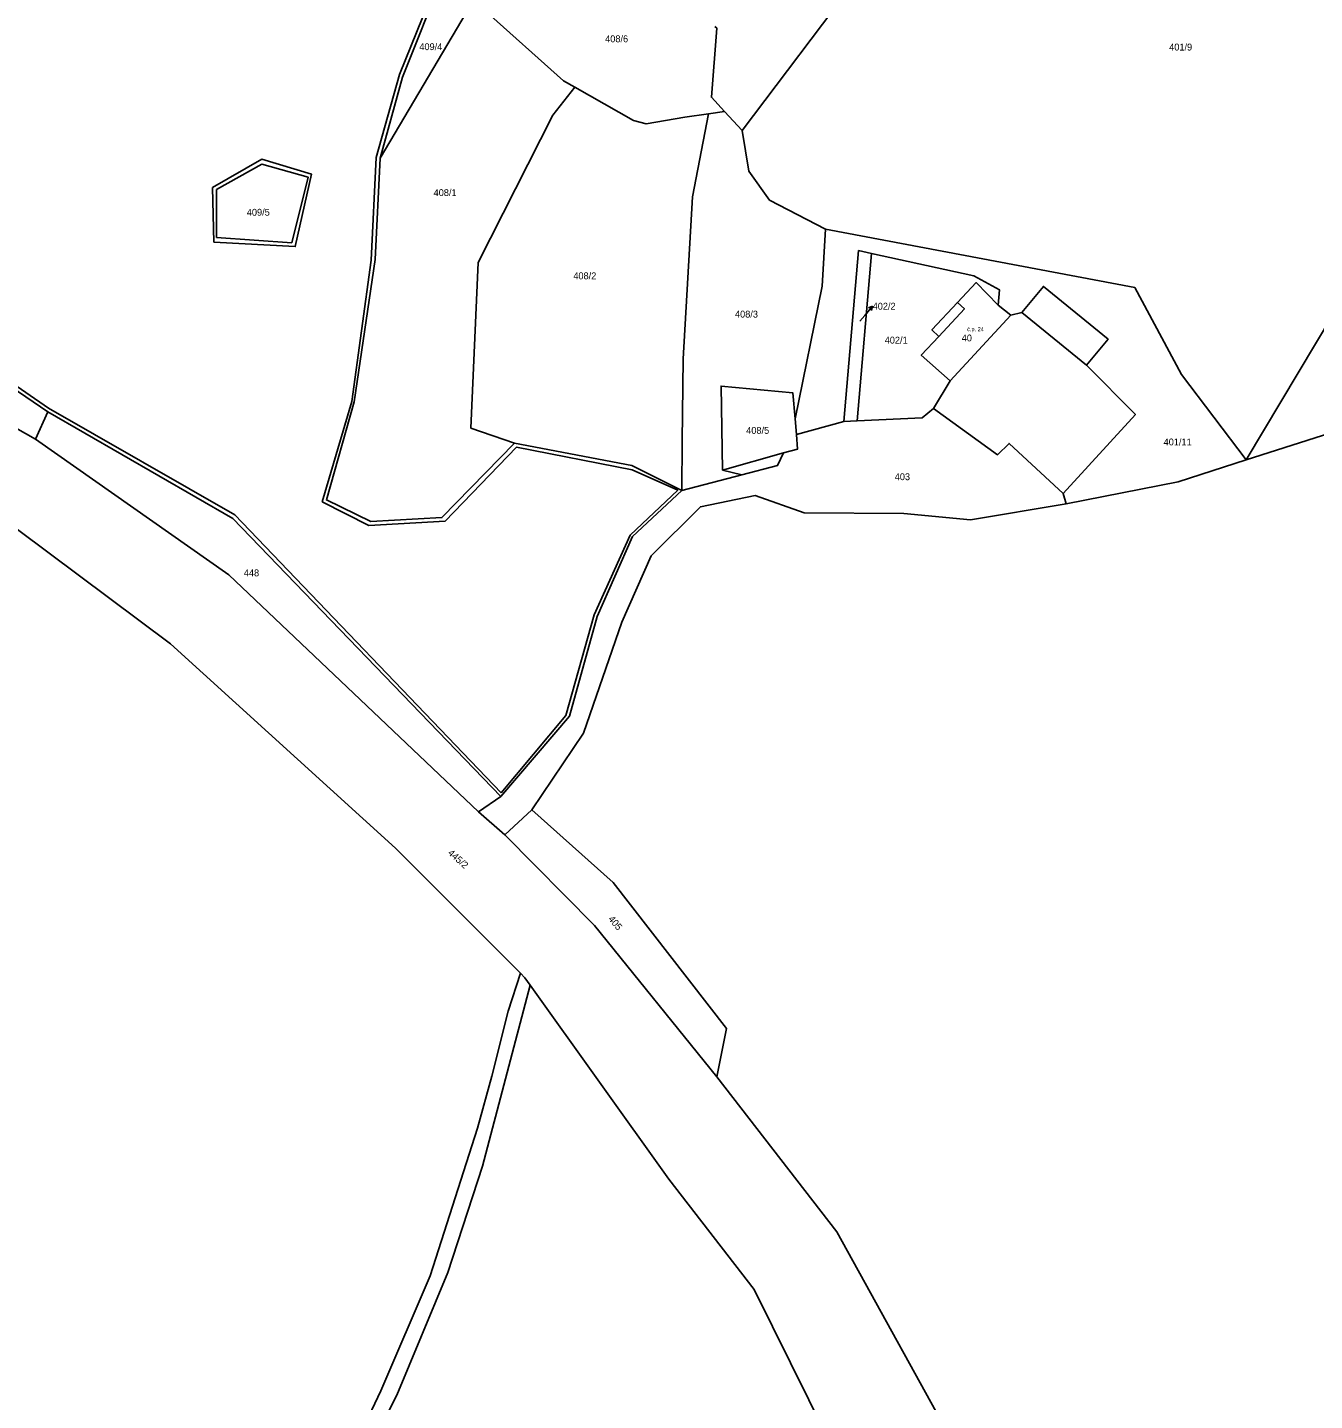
# Model space of a CAD drawing. Extents: x -880531 to -877616, y -1023932 to -1021350.
# Drawn here: x -879800.4 to -879481.6, y -1022931.1 to -1022591 of the extents above; entities that cross this region are included whole.
import ezdxf

# ---------------------------------------------------------------- set-up
doc = ezdxf.new("R2010")
doc.units = 0
for name, color, linetype in [('Definiční body', 7, 'Continuous'), ('Hranice parcel', 7, 'Continuous'), ('Parcelní čísla', 7, 'Continuous'), ('Polygon budovy', 7, 'Continuous'), ('Pop  PČ popisy', 7, 'Continuous'), ('Vnitřní kresba', 7, 'Continuous')]:
    doc.layers.add(name, color=color, linetype=linetype)

msp = doc.modelspace()

# ---------------------------------------------------------------- linework, layer by layer
at = {"layer": 'Hranice parcel'}
for p, q in [((-879690.46, -1022585.1), (-879713.01, -1022623.35)), ((-879627.75, -1022611.76), (-879631.75, -1022612.33)), ((-879623.38, -1022616.52), (-879627.75, -1022611.76)), ((-879602.75, -1022640.95), (-879526.13, -1022655.37)), ((-879591.34, -1022646.91), (-879594.93, -1022688.41)), ((-879565.99, -1022652.44), (-879591.34, -1022646.91)), ((-879526.13, -1022655.37), (-879514.57, -1022676.89)), ((-879514.57, -1022676.89), (-879498.53, -1022698.08)), ((-879798.38, -1022692.94), (-879795.38, -1022686.18)), ((-879609.96, -1022691.77), (-879610.29, -1022687.91)), ((-879598.23, -1022688.57), (-879609.96, -1022691.77)), ((-879598.23, -1022688.57), (-879594.93, -1022688.41)), ((-879464.76, -1022687.24), (-879498.53, -1022698.08)), ((-879623.49, -1022701.78), (-879638.33, -1022705.62)), ((-879543.1, -1022708.96), (-879543.91, -1022706.43)), ((-879683.13, -1022781.41), (-879688.66, -1022785.2)), ((-879688.66, -1022785.2), (-879682.17, -1022790.92)), ((-879682.17, -1022790.92), (-879675.47, -1022784.72))]:
    msp.add_line(p, q, dxfattribs=at)
for points in [[(-879623.38, -1022616.52), (-879595.05, -1022578.95), (-879583.42, -1022560.14), (-879547.99, -1022557.04), (-879563.05, -1022539.12)], [(-879713.01, -1022623.35), (-879707.48, -1022603.31), (-879697.33, -1022577.75), (-879700.32, -1022565.93)], [(-879664.81, -1022605.75), (-879667.6, -1022604.17), (-879687.23, -1022586.69), (-879690.46, -1022585.1)], [(-879630.14, -1022590.7), (-879629.68, -1022591.13), (-879630.98, -1022608.24), (-879627.75, -1022611.76)], [(-879419.69, -1022593.89), (-879443.01, -1022605.06), (-879498.53, -1022698.08)], [(-879679.75, -1022693.93), (-879690.55, -1022690.2), (-879688.76, -1022649.2), (-879670.29, -1022612.69), (-879664.81, -1022605.75)], [(-879631.75, -1022612.33), (-879637.58, -1022613.16), (-879647.13, -1022614.82), (-879650.28, -1022613.97), (-879664.81, -1022605.75)], [(-879941.5, -1022616.12), (-879936.23, -1022613.81), (-879891.4, -1022634.58), (-879829.75, -1022662.83), (-879795.38, -1022686.18)], [(-879638.33, -1022705.62), (-879638.26, -1022693.4), (-879638.01, -1022673.05), (-879635.66, -1022632.87), (-879631.75, -1022612.33)], [(-879602.75, -1022640.95), (-879616.61, -1022633.72), (-879621.74, -1022626.54), (-879623.38, -1022616.52)], [(-879798.38, -1022692.94), (-879884.35, -1022644.31), (-879942.81, -1022618.93)], [(-879730.87, -1022628.03), (-879734.93, -1022644.28), (-879753.58, -1022642.97), (-879753.59, -1022631.13), (-879742.39, -1022624.81), (-879730.87, -1022628.03)], [(-879713.01, -1022623.35), (-879714.28, -1022648.44), (-879719.47, -1022683.72), (-879726.35, -1022707.97), (-879715.36, -1022713.29), (-879697.76, -1022712.36), (-879679.75, -1022693.93)], [(-879610.29, -1022687.91), (-879603.57, -1022655.05), (-879602.75, -1022640.95)], [(-879591.34, -1022646.91), (-879594.55, -1022646.21), (-879598.23, -1022688.57)], [(-879559.99, -1022659.71), (-879559.65, -1022655.92), (-879565.99, -1022652.44)], [(-879559.99, -1022659.71), (-879565.45, -1022654.15), (-879570.05, -1022659.08), (-879576.4, -1022665.89), (-879574.7, -1022667.48), (-879579.01, -1022672.09), (-879571.87, -1022678.5), (-879576.02, -1022685.32)], [(-879538.12, -1022674.62), (-879532.76, -1022668.19), (-879548.77, -1022655.12), (-879554.14, -1022661.55), (-879556.82, -1022662.2), (-879559.99, -1022659.71)], [(-879543.91, -1022706.43), (-879525.98, -1022686.84), (-879538.12, -1022674.62)], [(-879623.49, -1022701.78), (-879628.23, -1022700.61), (-879628.62, -1022679.77), (-879610.83, -1022681.46), (-879610.29, -1022687.91)], [(-879678.3, -1022825.24), (-879709.21, -1022794.23), (-879764.96, -1022743.66), (-879810.51, -1022709.67), (-879851.64, -1022686.3)], [(-879795.38, -1022686.18), (-879749.57, -1022712.6), (-879683.13, -1022781.41)], [(-879594.93, -1022688.41), (-879578.78, -1022687.65), (-879576.02, -1022685.32)], [(-879576.02, -1022685.32), (-879560.13, -1022696.81), (-879557.28, -1022693.98), (-879543.91, -1022706.43)], [(-879688.66, -1022785.2), (-879750.57, -1022726.57), (-879798.38, -1022692.94)], [(-879609.96, -1022691.77), (-879609.65, -1022695.38), (-879613.14, -1022696.36)], [(-879679.75, -1022693.93), (-879650.7, -1022699.43), (-879638.33, -1022705.62)], [(-879613.14, -1022696.36), (-879614.59, -1022699.47), (-879623.49, -1022701.78)], [(-879498.53, -1022698.08), (-879515.41, -1022703.5), (-879543.1, -1022708.96)], [(-879638.33, -1022705.62), (-879650.55, -1022717.01), (-879659.28, -1022736.87), (-879666.18, -1022761.54), (-879683.13, -1022781.41)], [(-879543.1, -1022708.96), (-879566.85, -1022712.91), (-879583.37, -1022711.38), (-879608, -1022711.2), (-879620.16, -1022706.89), (-879633.72, -1022709.66), (-879645.89, -1022721.81), (-879653.22, -1022738.26), (-879662.7, -1022765.77), (-879675.47, -1022784.72)], [(-879675.47, -1022784.72), (-879655.37, -1022802.75), (-879627.29, -1022838.89), (-879629.68, -1022850.85)], [(-879682.17, -1022790.92), (-879659.92, -1022813.36), (-879629.68, -1022850.85)], [(-879727.7, -1022959.9), (-879712.9, -1022928.63), (-879700.69, -1022900.18), (-879688.97, -1022863.63), (-879685.42, -1022850.73), (-879681.37, -1022834.59), (-879678.3, -1022825.24)], [(-879678.3, -1022825.24), (-879677.2, -1022826.35), (-879675.88, -1022828.2)], [(-879675.88, -1022828.2), (-879687.7, -1022873.02), (-879696.29, -1022899.36), (-879708.92, -1022929.76), (-879721.2, -1022953.88)], [(-879527.34, -1023120.75), (-879542.22, -1023068.65), (-879565.2, -1023008.76), (-879588.79, -1022967.4), (-879620.45, -1022903.57), (-879641.51, -1022876.25), (-879675.88, -1022828.2)], [(-879629.68, -1022850.85), (-879599.95, -1022889.3), (-879568.31, -1022946.57), (-879542.1, -1022998.8), (-879521.22, -1023063.57), (-879503.92, -1023135.64), (-879493.69, -1023190.7), (-879490.49, -1023230.91), (-879486.76, -1023264.58)]]:
    msp.add_lwpolyline(points, dxfattribs=at)
at = {"layer": 'Polygon budovy'}
msp.add_lwpolyline([(-879579.01, -1022672.09), (-879571.87, -1022678.5), (-879556.82, -1022662.2), (-879559.99, -1022659.71), (-879565.45, -1022654.15), (-879570.05, -1022659.08), (-879568.35, -1022660.67), (-879574.7, -1022667.48)], close=True, dxfattribs=at)
at = {"layer": 'Pop  PČ popisy'}
for p, q in [((-879594.2, -1022663.68), (-879593.01, -1022662.28)), ((-879593.01, -1022662.28), (-879591.081, -1022659.981)), ((-879591.081, -1022659.981), (-879592.108, -1022660.426)), ((-879591.081, -1022659.981), (-879591.341, -1022661.07))]:
    msp.add_line(p, q, dxfattribs=at)
at = {"layer": 'Vnitřní kresba'}
for p, q in [((-879754.25, -1022644.13), (-879754.57, -1022630.61)), ((-879570.05, -1022659.08), (-879568.35, -1022660.67)), ((-879574.7, -1022667.48), (-879568.35, -1022660.67)), ((-879571.87, -1022678.5), (-879556.82, -1022662.2)), ((-879554.14, -1022661.55), (-879538.12, -1022674.62)), ((-879628.23, -1022700.61), (-879613.14, -1022696.36))]:
    msp.add_line(p, q, dxfattribs=at)
for points in [[(-879714.02, -1022623.13), (-879708.26, -1022602.63), (-879698.24, -1022577.81), (-879700.94, -1022566.36), (-879708.89, -1022563.02), (-879723.21, -1022561.27), (-879752.94, -1022559.2), (-879785.38, -1022553.47), (-879842.62, -1022544.57)], [(-879754.57, -1022630.61), (-879742.32, -1022623.61), (-879730.08, -1022627.27), (-879734.06, -1022645.25), (-879754.25, -1022644.13)], [(-879727.44, -1022708.44), (-879720.06, -1022683.58), (-879715.29, -1022648.59), (-879714.02, -1022623.13)], [(-879891.42, -1022633.68), (-879829.22, -1022661.84), (-879795.19, -1022685.23), (-879749.08, -1022711.64), (-879683.08, -1022780.5)], [(-879683.08, -1022780.5), (-879667.02, -1022761.41), (-879660.02, -1022736.44), (-879651.12, -1022716.71), (-879639.35, -1022705.58), (-879650.64, -1022700.49), (-879679.26, -1022694.92), (-879696.91, -1022713.21), (-879715.83, -1022714.33), (-879727.44, -1022708.44)]]:
    msp.add_lwpolyline(points, dxfattribs=at)

# ---------------------------------------------------------------- texts
at = {"layer": 'Definiční body'}
msp.add_text('č.p. 24', height=1, dxfattribs=at).set_placement((-879567.66, -1022666.19))
at = {"layer": 'Parcelní čísla'}
for s, p in [('409/4', (-879703.341, -1022596.57)), ('408/6', (-879657.318, -1022594.62)), ('401/9', (-879517.614, -1022596.67)), ('408/1', (-879699.81, -1022632.72)), ('409/5', (-879746.08, -1022637.59)), ('408/2', (-879665.2, -1022653.33)), ('402/2', (-879591.06, -1022660.85)), ('408/3', (-879625.16, -1022662.81)), ('402/1', (-879588.08, -1022669.26)), ('40', (-879569, -1022668.72)), ('408/5', (-879622.38, -1022691.61)), ('401/11', (-879518.994, -1022694.48)), ('403', (-879585.59, -1022703.09)), ('448', (-879746.82, -1022726.91))]:
    msp.add_text(s, height=1.7, dxfattribs=at).set_placement(p)
for s, rotation, p in [('445/2', 318, (-879696.388, -1022795.621)), ('405', 310, (-879656.661, -1022811.846))]:
    msp.add_text(s, height=1.7, rotation=rotation, dxfattribs=at).set_placement(p)

doc.saveas('drawing.dxf')
